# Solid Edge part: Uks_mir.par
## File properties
Author: Türk
Template: Iso Part.par
Last saved by: Türk
Revision: 10
Application: Solid Edge
Accuracy: 0,990
Username: Türk
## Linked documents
Uks.par
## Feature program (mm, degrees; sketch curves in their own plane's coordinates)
part copy "CopiedPart_1"
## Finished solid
Body 1: solid body, 127 faces, 381 edges, 252 vertices.
  Faces by surface: plane 60, spline 30, swept 14, blend 12, offset 7, cylinder 3, sphere 1
  Edges by curve: intersection 153, line 144, spline 45, curve on surface 29, circle 7, ellipse 3
Bounding box of the edges (mm; curved faces can reach further): 656.366 x 1000.758 x 806.222, from (-755.2336, -2100.4958, 144.8721) to (-98.8677, -1099.7378, 951.0944).
Cylindrical faces by radius (mm): R746.2548 x1, R1779.5305 x1, R73875.9026 x1
Spherical faces by radius (mm): R5 x1
Planar faces by outward normal: +x 5, +y 6, +z 2, -x 6, -y 9, -z 5, oblique 27
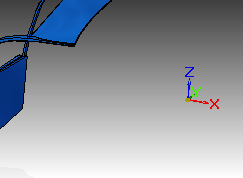
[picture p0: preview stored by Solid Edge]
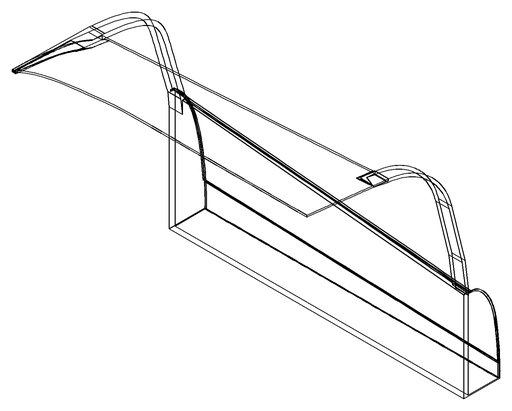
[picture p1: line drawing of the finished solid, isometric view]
